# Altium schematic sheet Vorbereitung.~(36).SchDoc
size A4
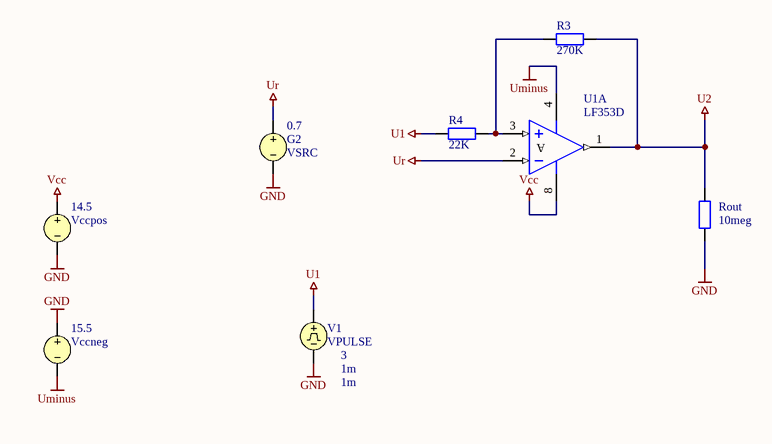
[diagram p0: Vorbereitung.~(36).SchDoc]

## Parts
G2  VSRC  value 0.7
R3  value 270K  [AXIAL-0.4]  (hidden comment: Res2)
R4  value 22K  [AXIAL-0.4]  (hidden comment: Res2)
Rout  value 10meg  [AXIAL-0.4]  (hidden comment: Res2)
U1  LF353D  [D008_L]  (part A of 2)
V1  VPULSE  AC Magnitude: 3  Rise Time: 1m
Vccneg  value 15.5  (hidden comment: VSRC)
Vccpos  value 14.5  (hidden comment: VSRC)

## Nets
GND: G2.2 Rout.1 V1.2 Vccneg.1 Vccpos.2
U1: R4.2 V1.1
U2: R3.1 Rout.2 U1.1(OUT)
Uminus: U1.4(V-) Vccneg.2
Ur: G2.1 U1.2(IN-)
Vcc: U1.8(V+) Vccpos.1
NetR3_2: R3.2 R4.1 U1.3(IN+)

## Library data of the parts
G2 Vccneg Vccpos = VSRC: Voltage Source; Note: PCB Footprint - Not required
R3 R4 Rout = Res2: Resistor
U1 = LF353D: Dual Operational Amplifier
V1 = VPULSE: Pulse Voltage Source; Note: PCB Footprint - Not required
